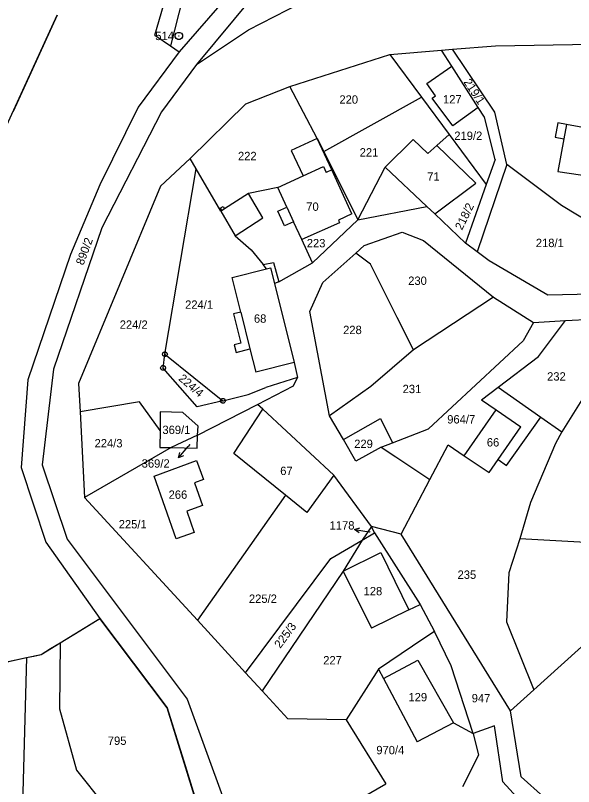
# Model space of a CAD drawing. Extents: x -593358 to -590116, y -1072518 to -1068420.
# Drawn here: x -592072.6 to -591959.1, y -1071067.8 to -1070910.9 of the extents above; entities that cross this region are included whole.
import ezdxf

# ---------------------------------------------------------------- set-up
doc = ezdxf.new("R2010")
doc.units = 0
for name, color, linetype in [('Parcela KN', 7, 'Continuous'), ('Parcelní číslo', 7, 'Continuous'), ('Parcelní číslo_stavební', 7, 'Continuous'), ('stavby - vnitřní kresba', 7, 'Continuous'), ('Vnitřní obvod', 7, 'Continuous'), ('Vrstva 16', 7, 'Continuous'), ('Vrstva 17', 7, 'Continuous'), ('Vrstva 24', 7, 'Continuous')]:
    doc.layers.add(name, color=color, linetype=linetype)

msp = doc.modelspace()

# ---------------------------------------------------------------- linework, layer by layer
at = {"layer": 'Parcela KN'}
for p, q in [((-592044.25, -1070914.9), (-592029.91, -1070865.59)), ((-592013.86, -1070894.42), (-592035.77, -1070920.86)), ((-592035.98, -1070896.91), (-592041.08, -1070917.09)), ((-592022.86, -1070899.35), (-592039.31, -1070918.31)), ((-592025.24, -1070913.83), (-592014.65, -1070908.37)), ((-592082.11, -1070949.99), (-592064.12, -1070910.82)), ((-592035.77, -1070920.86), (-592025.24, -1070913.83)), ((-592044.25, -1070914.9), (-592041.08, -1070917.09)), ((-592041.08, -1070917.09), (-592039.31, -1070918.31)), ((-591985.93, -1070917.96), (-591983.68, -1070917.77)), ((-591983.68, -1070917.77), (-591974.96, -1070917.04)), ((-591975.08, -1070930.57), (-591983.68, -1070917.77)), ((-591974.96, -1070917.04), (-591934.16, -1070916.43)), ((-592039.31, -1070918.31), (-592047.68, -1070929.53)), ((-592016.83, -1070925.32), (-591996.47, -1070918.85)), ((-591996.47, -1070918.85), (-591985.93, -1070917.96)), ((-591996.47, -1070918.85), (-591990.04, -1070927.52)), ((-591983.84, -1070921.23), (-591985.93, -1070917.96)), ((-592035.77, -1070920.86), (-592042.93, -1070930.49)), ((-591988.92, -1070924.74), (-591983.84, -1070921.23)), ((-591978.48, -1070929.59), (-591983.84, -1070921.23)), ((-592025.72, -1070928.88), (-592016.83, -1070925.32)), ((-592011.21, -1070935.9), (-592016.83, -1070925.32)), ((-591987.2, -1070927.22), (-591988.92, -1070924.74)), ((-591987.85, -1070927.7), (-591987.2, -1070927.22)), ((-592009.88, -1070938.58), (-591990.04, -1070927.52)), ((-591990.04, -1070927.52), (-591984.4, -1070935.11)), ((-591983.67, -1070933.36), (-591987.85, -1070927.7)), ((-592047.68, -1070929.53), (-592055.42, -1070945.37)), ((-592037.07, -1070940.01), (-592025.72, -1070928.88)), ((-591978.48, -1070929.59), (-591983.67, -1070933.36)), ((-591977.21, -1070931.57), (-591978.48, -1070929.59)), ((-592042.93, -1070930.49), (-592055.05, -1070954.09)), ((-591975, -1070940.22), (-591977.21, -1070931.57)), ((-591972.65, -1070941.24), (-591975.08, -1070930.57)), ((-591962.29, -1070932.72), (-591962.83, -1070935.67)), ((-591960.52, -1070933.05), (-591962.29, -1070932.72)), ((-591949.91, -1070935.01), (-591960.52, -1070933.05)), ((-591986.87, -1070937.33), (-591984.4, -1070935.11)), ((-591984.4, -1070935.11), (-591976.83, -1070945.31)), ((-592011.21, -1070935.9), (-592016.5, -1070938.34)), ((-592008.29, -1070942.31), (-592011.21, -1070935.9)), ((-592011.21, -1070935.9), (-592009.88, -1070938.58)), ((-591997.4, -1070941.76), (-591991.68, -1070936.09)), ((-591991.68, -1070936.09), (-591988.73, -1070939)), ((-591962.83, -1070935.67), (-591961.07, -1070936)), ((-591961.07, -1070936), (-591962.3, -1070942.64)), ((-591988.73, -1070939), (-591986.87, -1070937.33)), ((-591978.99, -1070944.98), (-591986.87, -1070937.33)), ((-592016.5, -1070938.34), (-592014.11, -1070943.52)), ((-592009.88, -1070938.58), (-592002.99, -1070952.47)), ((-592037.07, -1070940.01), (-592043.1, -1070945.64)), ((-592035.83, -1070942.12), (-592037.07, -1070940.01)), ((-591972.65, -1070941.24), (-591978.69, -1070958.98)), ((-591975, -1070940.22), (-591976.83, -1070945.31)), ((-591961.55, -1070949.52), (-591972.65, -1070941.24)), ((-592042.22, -1070979.81), (-592035.83, -1070942.12)), ((-592030.83, -1070950.73), (-592035.83, -1070942.12)), ((-592004.21, -1070951.25), (-592008.29, -1070942.31)), ((-592002.99, -1070952.47), (-591997.4, -1070941.76)), ((-591962.3, -1070942.64), (-591951.62, -1070944.21)), ((-592019.25, -1070945.89), (-592014.11, -1070943.52)), ((-592055.42, -1070945.37), (-592061.44, -1070959.49)), ((-592043.1, -1070945.64), (-592059.81, -1070985.75)), ((-592019.25, -1070945.89), (-592025.2, -1070947.13)), ((-591987.33, -1070951.26), (-591978.99, -1070944.98)), ((-591976.83, -1070945.31), (-591981.09, -1070957.18)), ((-592025.2, -1070947.13), (-592030.07, -1070950.24)), ((-592030.94, -1070950.06), (-592030.39, -1070949.74)), ((-592030.58, -1070950.57), (-592030.94, -1070950.06)), ((-592030.58, -1070950.57), (-592030.83, -1070950.73)), ((-592030.83, -1070950.73), (-592027.93, -1070955.7)), ((-592030.39, -1070949.74), (-592030.07, -1070950.24)), ((-592002.99, -1070952.47), (-591988.95, -1070949.74)), ((-591987.33, -1070951.26), (-591988.95, -1070949.74)), ((-591953.07, -1070954.75), (-591961.55, -1070949.52)), ((-592004.21, -1070951.25), (-592006.93, -1070952.5)), ((-591981.09, -1070957.18), (-591987.33, -1070951.26)), ((-592006.67, -1070953.08), (-592014.38, -1070956.44)), ((-592012.16, -1070961.18), (-592002.99, -1070952.47)), ((-592006.93, -1070952.5), (-592006.67, -1070953.08)), ((-592055.05, -1070954.09), (-592064.91, -1070982.87)), ((-592001.65, -1070957.67), (-591993.93, -1070954.95)), ((-591993.93, -1070954.95), (-591989.58, -1070956.7)), ((-592027.93, -1070955.7), (-592024.64, -1070958.59)), ((-592012.16, -1070961.18), (-592014.38, -1070956.44)), ((-591989.58, -1070956.7), (-591975.38, -1070968.18)), ((-592024.64, -1070958.59), (-592022.23, -1070961.57)), ((-592003.39, -1070959.23), (-592001.65, -1070957.67)), ((-591978.69, -1070958.98), (-591981.09, -1070957.18)), ((-592061.44, -1070959.49), (-592070.08, -1070985.01)), ((-592010.11, -1070965.22), (-592003.39, -1070959.23)), ((-592000.41, -1070961.5), (-592003.39, -1070959.23)), ((-591976.24, -1070960.82), (-591978.69, -1070958.98)), ((-592022.23, -1070961.57), (-592020.11, -1070961.12)), ((-592021.52, -1070962.41), (-592022.23, -1070961.57)), ((-592020.11, -1070961.12), (-592019.06, -1070965.09)), ((-592019.06, -1070965.09), (-592012.16, -1070961.18)), ((-591994.96, -1070972.3), (-592000.41, -1070961.5)), ((-591964.29, -1070967.82), (-591976.24, -1070960.82)), ((-592028.54, -1070964.19), (-592021.52, -1070962.41)), ((-592026.77, -1070971.27), (-592028.54, -1070964.19)), ((-592019.06, -1070965.09), (-592019.95, -1070965.41)), ((-592019.95, -1070965.41), (-592015.92, -1070981.49)), ((-592012.75, -1070971.09), (-592010.11, -1070965.22)), ((-591954.31, -1070967.54), (-591964.29, -1070967.82)), ((-591975.38, -1070968.18), (-591991.65, -1070978.89)), ((-591975.38, -1070968.18), (-591967.2, -1070973.32)), ((-592008.73, -1070992.32), (-592012.75, -1070971.09)), ((-592026.77, -1070971.27), (-592028.28, -1070971.62)), ((-592028.28, -1070971.62), (-592026.77, -1070977.53)), ((-591991.65, -1070978.89), (-591994.96, -1070972.3)), ((-591960.7, -1070972.96), (-591945.06, -1070972.11)), ((-591967.2, -1070973.32), (-591969.32, -1070977.11)), ((-591967.2, -1070973.32), (-591960.7, -1070972.96)), ((-591966.24, -1070980.29), (-591960.7, -1070972.96)), ((-591969.32, -1070977.11), (-591988.57, -1070995.01)), ((-592026.77, -1070977.53), (-592028.13, -1070977.88)), ((-592028.13, -1070977.88), (-592027.73, -1070979.43)), ((-592027.73, -1070979.43), (-592024.92, -1070978.71)), ((-592024.92, -1070978.71), (-592023.71, -1070983.46)), ((-591991.65, -1070978.89), (-592000.34, -1070986.38)), ((-592042.58, -1070982.61), (-592042.22, -1070979.81)), ((-592042.22, -1070979.81), (-592030.4, -1070989.27)), ((-591974.4, -1070986.48), (-591966.24, -1070980.29)), ((-592015.92, -1070981.49), (-592023.71, -1070983.46)), ((-592015.92, -1070981.49), (-592015.22, -1070984.55)), ((-592064.91, -1070982.87), (-592067.15, -1071002.3)), ((-592035.64, -1070990.49), (-592042.58, -1070982.61)), ((-591953.7, -1070983.06), (-591961.5, -1070995.62)), ((-592070.08, -1070985.01), (-592071.48, -1071002.87)), ((-592015.22, -1070984.55), (-592021.69, -1070986.55)), ((-592016.05, -1070986.22), (-592015.22, -1070984.55)), ((-592059.81, -1070985.75), (-592059.46, -1070991.51)), ((-592025.28, -1070988.02), (-592021.69, -1070986.55)), ((-592023.37, -1070990), (-592016.05, -1070986.22)), ((-592000.34, -1070986.38), (-592008.73, -1070992.32)), ((-591977.82, -1070989.07), (-591974.4, -1070986.48)), ((-591974.4, -1070986.48), (-591965.77, -1070992.59)), ((-592030.4, -1070989.27), (-592025.28, -1070988.02)), ((-592047.4, -1070989.47), (-592059.46, -1070991.51)), ((-592043.21, -1070995.31), (-592047.4, -1070989.47)), ((-592030.4, -1070989.27), (-592035.64, -1070990.49)), ((-592035.55, -1070996.29), (-592023.37, -1070990)), ((-592022.29, -1070990.98), (-592023.37, -1070990)), ((-591977.82, -1070989.07), (-591974.86, -1070991.1)), ((-592059.46, -1070991.51), (-592058.54, -1071008.96)), ((-592043.15, -1070991.51), (-592043.21, -1070995.31)), ((-592038.57, -1070991.68), (-592043.15, -1070991.51)), ((-592028.2, -1070999.97), (-592022.29, -1070990.98)), ((-592022.29, -1070990.98), (-592007.88, -1071004.44)), ((-591981.34, -1071000.48), (-591974.86, -1070991.1)), ((-592035.45, -1070994.42), (-592038.57, -1070991.68)), ((-592005.86, -1070997.13), (-592008.73, -1070992.32)), ((-592005.86, -1070997.13), (-591998.35, -1070992.91)), ((-591998.35, -1070992.91), (-591995.94, -1070997.82)), ((-591972.72, -1071002.43), (-591965.77, -1070992.59)), ((-591965.77, -1070992.59), (-591961.5, -1070995.62)), ((-592035.55, -1070996.29), (-592035.45, -1070994.42)), ((-592043.21, -1070995.31), (-592043.26, -1070998.77)), ((-592035.55, -1070996.29), (-592040.92, -1070998.81)), ((-592035.68, -1070998.89), (-592035.55, -1070996.29)), ((-591995.94, -1070997.82), (-591988.57, -1070995.01)), ((-591961.5, -1070995.62), (-591962.74, -1070997.98)), ((-592003.38, -1071001.54), (-592005.86, -1070997.13)), ((-591998.22, -1070998.69), (-591995.94, -1070997.82)), ((-592040.92, -1070998.81), (-592058.54, -1071008.96)), ((-592043.26, -1070998.77), (-592040.92, -1070998.81)), ((-592040.92, -1070998.81), (-592035.68, -1070998.89)), ((-591998.22, -1070998.69), (-592003.38, -1071001.54)), ((-591998.22, -1070998.69), (-591995.22, -1071000.69)), ((-591988.32, -1071005.3), (-591984.62, -1070998.27)), ((-591984.62, -1070998.27), (-591981.34, -1071000.48)), ((-591962.74, -1070997.98), (-591967.84, -1071009.95)), ((-592017.67, -1071008.47), (-592028.2, -1070999.97)), ((-591995.22, -1071000.69), (-591988.32, -1071005.3)), ((-591981.34, -1071000.48), (-591976.28, -1071003.89)), ((-592067.15, -1071002.3), (-592062.07, -1071017.45)), ((-592044.42, -1071004.6), (-592035.77, -1071001.45)), ((-592035.77, -1071001.45), (-592034.36, -1071005.32)), ((-591976.28, -1071003.89), (-591974.42, -1071001.2)), ((-591974.42, -1071001.2), (-591972.72, -1071002.43)), ((-592071.48, -1071002.87), (-592066.44, -1071018.03)), ((-592039.9, -1071017.35), (-592044.42, -1071004.6)), ((-592034.36, -1071005.32), (-592036.19, -1071005.99)), ((-592007.88, -1071004.44), (-592013.32, -1071011.98)), ((-592000.22, -1071014.84), (-592007.88, -1071004.44)), ((-591994.17, -1071016.43), (-591988.32, -1071005.3)), ((-592036.19, -1071005.99), (-592034.55, -1071010.61)), ((-592017.67, -1071008.47), (-592035.61, -1071033.94)), ((-592013.32, -1071011.98), (-592017.67, -1071008.47)), ((-592058.54, -1071008.96), (-592035.61, -1071033.94)), ((-591967.84, -1071009.95), (-591969.99, -1071017.38)), ((-592034.55, -1071010.61), (-592037.78, -1071011.75)), ((-592037.78, -1071011.75), (-592036.25, -1071016.06)), ((-592000.22, -1071014.84), (-592002.06, -1071017.6)), ((-591999.6, -1071016.16), (-592000.22, -1071014.84)), ((-591994.17, -1071016.43), (-592000.22, -1071014.84)), ((-592036.25, -1071016.06), (-592039.9, -1071017.35)), ((-592002.06, -1071017.6), (-591999.6, -1071016.16)), ((-591999.6, -1071016.16), (-591990.32, -1071030.7)), ((-591971.9, -1071052.36), (-591994.17, -1071016.43)), ((-592066.44, -1071018.03), (-592055.48, -1071033.57)), ((-592062.07, -1071017.45), (-592037.69, -1071049.99)), ((-592008.43, -1071021.33), (-592002.06, -1071017.6)), ((-592002.06, -1071017.6), (-592005.93, -1071023.92)), ((-591969.99, -1071017.38), (-591972.25, -1071024.31)), ((-591940.2, -1071019.06), (-591969.99, -1071017.38)), ((-592025.8, -1071044.62), (-592008.43, -1071021.33)), ((-592005.93, -1071023.92), (-592022.46, -1071048.26)), ((-592005.93, -1071023.92), (-592000.19, -1071035.54)), ((-591972.25, -1071024.31), (-591972.74, -1071034.24)), ((-591967.16, -1071048.07), (-591944.52, -1071027.57)), ((-591992.56, -1071031.79), (-591990.32, -1071030.7)), ((-591990.32, -1071030.7), (-591987.37, -1071036.21)), ((-591992.56, -1071031.79), (-592000.19, -1071035.54)), ((-592063.53, -1071038.52), (-592055.48, -1071033.57)), ((-592041.76, -1071051.75), (-592055.48, -1071033.57)), ((-592035.61, -1071033.94), (-592025.8, -1071044.62)), ((-591972.74, -1071034.24), (-591967.16, -1071048.07)), ((-591987.37, -1071036.21), (-591989.56, -1071037.67)), ((-591983.95, -1071043.18), (-591987.37, -1071036.21)), ((-592067.4, -1071040.89), (-592063.53, -1071038.52)), ((-592063.53, -1071038.52), (-592063.63, -1071051.96)), ((-591989.56, -1071037.67), (-591998.79, -1071043.86)), ((-592083.85, -1071044.42), (-592070.34, -1071041.52)), ((-592070.34, -1071041.52), (-592071.71, -1071089.57)), ((-592070.34, -1071041.52), (-592067.4, -1071040.89)), ((-591979.5, -1071056.98), (-591983.95, -1071043.18)), ((-592022.46, -1071048.26), (-592025.8, -1071044.62)), ((-591998.79, -1071043.86), (-592005.32, -1071054.21)), ((-591998.79, -1071043.86), (-591997.75, -1071045.79)), ((-591997.75, -1071045.79), (-591990.87, -1071058.67)), ((-591971.9, -1071052.36), (-591967.16, -1071048.07)), ((-592017.24, -1071053.99), (-592022.46, -1071048.26)), ((-592037.69, -1071049.99), (-592030.26, -1071070.45)), ((-592063.63, -1071051.96), (-592060.18, -1071064.4)), ((-592034.48, -1071075.16), (-592041.76, -1071051.75)), ((-591969.75, -1071065.76), (-591971.9, -1071052.36)), ((-592005.32, -1071054.21), (-592017.24, -1071053.99)), ((-592005.32, -1071054.21), (-591997.3, -1071067.19)), ((-591983.54, -1071054.79), (-591990.87, -1071058.67)), ((-591983.54, -1071054.79), (-591979.5, -1071056.98)), ((-591975.19, -1071055.38), (-591979.5, -1071056.98)), ((-591973.5, -1071066.79), (-591975.19, -1071055.38)), ((-591979.5, -1071056.98), (-591978.42, -1071061.35)), ((-591978.42, -1071061.35), (-591981.68, -1071067.82)), ((-592060.18, -1071064.4), (-592042.61, -1071086.58)), ((-591967.22, -1071073.6), (-591973.5, -1071066.79)), ((-591965.21, -1071069.85), (-591969.75, -1071065.76)), ((-592002.07, -1071069.98), (-591997.3, -1071067.19))]:
    msp.add_line(p, q, dxfattribs=at)
at = {"layer": 'stavby - vnitřní kresba'}
for p, q in [((-591960.52, -1070933.05), (-591961.07, -1070936)), ((-592014.11, -1070943.52), (-592009.98, -1070941.59)), ((-592009.98, -1070941.59), (-592009.4, -1070942.83)), ((-592008.29, -1070942.31), (-592009.4, -1070942.83)), ((-591988.95, -1070949.74), (-591997.4, -1070941.76)), ((-592017.44, -1070949.9), (-592019.25, -1070945.89)), ((-592022.32, -1070952.07), (-592025.2, -1070947.13)), ((-592030.07, -1070950.24), (-592030.58, -1070950.57)), ((-592019.26, -1070950.73), (-592017.44, -1070949.9)), ((-592017.89, -1070953.69), (-592019.26, -1070950.73)), ((-592017.44, -1070949.9), (-592016.04, -1070952.86)), ((-592027.93, -1070955.7), (-592022.32, -1070952.07)), ((-592016.04, -1070952.86), (-592017.89, -1070953.69)), ((-592014.38, -1070956.44), (-592016.04, -1070952.86)), ((-592021.52, -1070962.41), (-592020.75, -1070962.21)), ((-592020.75, -1070962.21), (-592019.95, -1070965.41)), ((-592026.77, -1070971.27), (-592024.92, -1070978.71)), ((-591974.86, -1070991.1), (-591969.82, -1070994.56)), ((-591974.42, -1071001.2), (-591969.82, -1070994.56)), ((-592005.93, -1071023.92), (-591998.32, -1071020.14)), ((-591998.32, -1071020.14), (-591992.56, -1071031.79)), ((-591997.75, -1071045.79), (-591990.75, -1071042.05)), ((-591990.75, -1071042.05), (-591983.54, -1071054.79))]:
    msp.add_line(p, q, dxfattribs=at)
at = {"layer": 'Vnitřní obvod'}
for points in [[(-592064.12, -1070910.82), (-592073.115, -1070930.405)], [(-592077.095, -1071042.97), (-592070.34, -1071041.52), (-592068.87, -1071041.205), (-592067.4, -1071040.89), (-592065.465, -1071039.705), (-592063.53, -1071038.52), (-592059.505, -1071036.045), (-592055.48, -1071033.57)], [(-592055.48, -1071033.57), (-592048.62, -1071042.66), (-592041.76, -1071051.75), (-592038.12, -1071063.455), (-592034.48, -1071075.16), (-592029.325, -1071085.425), (-592024.17, -1071095.69), (-592023.73, -1071096.565), (-592023.73, -1071096.565), (-592023.29, -1071097.44), (-592021.055, -1071095.87), (-592018.82, -1071094.3)]]:
    msp.add_lwpolyline(points, dxfattribs=at)
at = {"layer": 'Vrstva 16'}
for p, q in [((-592039.426, -1071000.899), (-592037.51, -1070998.59)), ((-592037.14, -1070998.15), (-592037.51, -1070998.59)), ((-592003.617, -1071015.466), (-592000.66, -1071015.97)), ((-592000.45, -1071016.01), (-592000.66, -1071015.97))]:
    msp.add_line(p, q, dxfattribs=at)
for points in [[(-592038.402, -1071000.448), (-592039.426, -1071000.899), (-592039.172, -1070999.81)], [(-592002.716, -1071016.127), (-592003.617, -1071015.466), (-592002.548, -1071015.141)]]:
    msp.add_lwpolyline(points, dxfattribs=at)
at = {"layer": 'Vrstva 24'}
for p, q in [((-592039.43, -1070915.05), (-592039.33, -1070915.05)), ((-592042.34, -1070979.81), (-592042.1, -1070979.81)), ((-592042.7, -1070982.61), (-592042.46, -1070982.61)), ((-592030.52, -1070989.27), (-592030.28, -1070989.27))]:
    msp.add_line(p, q, dxfattribs=at)
for points in [[(-592039.19, -1070914.33), (-592038.85, -1070914.52), (-592038.66, -1070914.86), (-592038.66, -1070915.25), (-592038.85, -1070915.59), (-592039.19, -1070915.78), (-592039.58, -1070915.78), (-592039.92, -1070915.59), (-592040.11, -1070915.25), (-592040.11, -1070914.86), (-592039.92, -1070914.52), (-592039.58, -1070914.33)], [(-592042.07, -1070979.33), (-592041.82, -1070979.51), (-592041.72, -1070979.8), (-592041.82, -1070980.09), (-592042.07, -1070980.27), (-592042.38, -1070980.27), (-592042.63, -1070980.09), (-592042.73, -1070979.8), (-592042.63, -1070979.51), (-592042.38, -1070979.33)], [(-592042.43, -1070982.13), (-592042.18, -1070982.31), (-592042.08, -1070982.6), (-592042.18, -1070982.89), (-592042.43, -1070983.07), (-592042.74, -1070983.07), (-592042.99, -1070982.89), (-592043.09, -1070982.6), (-592042.99, -1070982.31), (-592042.74, -1070982.13)], [(-592030.25, -1070988.79), (-592030, -1070988.97), (-592029.9, -1070989.26), (-592030, -1070989.55), (-592030.25, -1070989.73), (-592030.56, -1070989.73), (-592030.81, -1070989.55), (-592030.91, -1070989.26), (-592030.81, -1070988.97), (-592030.56, -1070988.79)]]:
    msp.add_lwpolyline(points, close=True, dxfattribs=at)

# ---------------------------------------------------------------- texts
at = {"layer": 'Parcelní číslo'}
for s, rotation, p in [('219/1', 303.32386, (-591981.534, -1070924.431)), ('218/2', 63.94209, (-591981.772, -1070954.688)), ('890/2', 69.49978, (-592058.807, -1070961.815)), ('224/4', 319.42397, (-592039.579, -1070984.961)), ('225/3', 53.62885, (-592018.743, -1071039.761))]:
    msp.add_text(s, height=1.7, rotation=rotation, dxfattribs=at).set_placement(p)
for s, height, p in [('220', 1.7, (-592006.718, -1070928.84)), ('219/2', 1.7, (-591983.342, -1070936.21)), ('221', 1.7, (-592002.593, -1070939.59)), ('222', 1.7, (-592027.345, -1070940.33)), ('223', 1.7, (-592013.359, -1070958.06)), ('218/1', 1.7, (-591966.758, -1070958.01)), ('230', 1.7, (-591992.722, -1070965.7)), ('224/1', 1.7, (-592038.102, -1070970.56)), ('224/2', 1.7, (-592051.404, -1070974.63)), ('228', 1.7, (-592005.962, -1070975.71)), ('232', 1.7, (-591964.469, -1070985.17)), ('231', 1.7, (-591993.857, -1070987.72)), ('964/7', 1.7, (-591984.783, -1070993.9)), ('224/3', 1.7, (-592056.527, -1070998.76)), ('229', 1.7, (-592003.711, -1070998.89)), ('225/1', 1.7, (-592051.609, -1071015.24)), ('1178', 0.1, (-592000.563, -1071016.01)), ('235', 1.7, (-591982.682, -1071025.5)), ('225/2', 1.7, (-592025.121, -1071030.39)), ('227', 1.7, (-592010.011, -1071042.91)), ('947', 1.7, (-591979.804, -1071050.62)), ('795', 1.7, (-592053.831, -1071059.28)), ('970/4', 1.7, (-591999.21, -1071061.19))]:
    msp.add_text(s, height=height, dxfattribs=at).set_placement(p)
at = {"layer": 'Parcelní číslo_stavební'}
for s, height, p in [('127', 1.7, (-591985.64, -1070928.79)), ('71', 1.7, (-591988.857, -1070944.5)), ('70', 1.7, (-592013.461, -1070950.63)), ('68', 1.7, (-592024.105, -1070973.4)), ('369/1', 1.7, (-592042.722, -1070996.04)), ('66', 1.7, (-591976.725, -1070998.58)), ('369/2', 0.1, (-592037.351, -1070998.15)), ('67', 1.7, (-592018.755, -1071004.38)), ('266', 1.7, (-592041.458, -1071009.22)), ('128', 1.7, (-592001.8, -1071028.85)), ('129', 1.7, (-591992.67, -1071050.42))]:
    msp.add_text(s, height=height, dxfattribs=at).set_placement(p)
at = {"layer": 'Vrstva 16'}
for s, p in [('369/2', (-592046.936, -1071002.88)), ('1178', (-592008.713, -1071015.47))]:
    msp.add_text(s, height=1.7, dxfattribs=at).set_placement(p)
at = {"layer": 'Vrstva 17'}
msp.add_text('514', height=1.7, dxfattribs=at).set_placement((-592044.17, -1070915.9))

doc.saveas('drawing.dxf')
